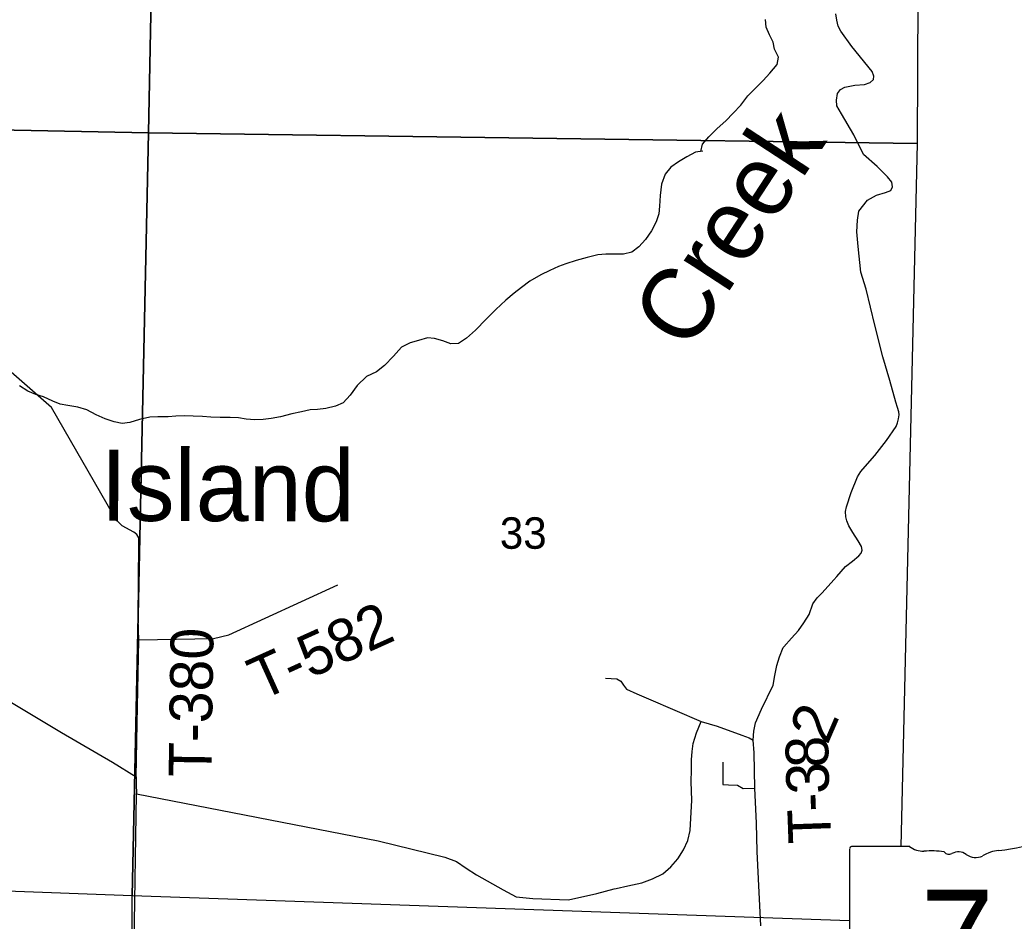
# Model space of a CAD drawing. Extents: x 0 to 34, y 0 to 22.
# Drawn here: x 6.245 to 7.567, y 15.005 to 16.204 of the extents above; entities that cross this region are included whole.
import ezdxf

# ---------------------------------------------------------------- set-up
doc = ezdxf.new("R2010")
doc.units = 0
for name, color, linetype in [('Default', 7, 'Continuous'), ('GM_X_Minor_River', 7, 'Continuous'), ('GM_X_Minor_River_Text', 7, 'Continuous'), ('GM_X_Section', 7, 'Continuous'), ('GM_X_Section_Text', 7, 'Continuous'), ('GM_X_State_Shield', 7, 'Continuous'), ('GM_X_Township_Road', 7, 'Continuous'), ('GM_X_Township_Road_Text', 7, 'Continuous')]:
    doc.layers.add(name, color=color, linetype=linetype)

msp = doc.modelspace()

# ---------------------------------------------------------------- linework, layer by layer
at = {"layer": 'Default'}
for p, q in [((6.3944, 15.0386), (5.4229, 15.0756)), ((6.3909, 14.1), (6.3944, 15.0386))]:
    msp.add_line(p, q, dxfattribs=at)
at = {"layer": 'GM_X_Minor_River'}
for p, q in [((7.2369, 16.1939), (7.2363, 16.2042)), ((7.2414, 16.1838), (7.2369, 16.1939)), ((7.2466, 16.174), (7.2414, 16.1838)), ((7.248, 16.1645), (7.2466, 16.174)), ((7.2536, 16.154), (7.248, 16.1645)), ((7.2519, 16.1441), (7.2536, 16.154)), ((7.242, 16.1328), (7.2519, 16.1441)), ((7.2331, 16.123), (7.242, 16.1328)), ((7.2128, 16.1027), (7.2231, 16.1129)), ((7.2231, 16.1129), (7.2331, 16.123)), ((7.2036, 16.0903), (7.2128, 16.1027)), ((7.1933, 16.0793), (7.2036, 16.0903)), ((7.1836, 16.0695), (7.1933, 16.0793)), ((7.1607, 16.048), (7.1718, 16.0593)), ((7.1718, 16.0593), (7.1836, 16.0695)), ((7.1526, 16.0383), (7.1607, 16.048)), ((7.1501, 16.0287), (7.1526, 16.0383)), ((7.1316, 16.0215), (7.1204, 16.0147)), ((7.1432, 16.0276), (7.1316, 16.0215)), ((7.1527, 16.0291), (7.1432, 16.0276)), ((7.1103, 16.0079), (7.1027, 15.9982)), ((7.1204, 16.0147), (7.1103, 16.0079)), ((7.1027, 15.9982), (7.0981, 15.9851)), ((7.0981, 15.9851), (7.0963, 15.9702)), ((7.0963, 15.9702), (7.0952, 15.9557)), ((7.0952, 15.9557), (7.0944, 15.9458)), ((7.0944, 15.9458), (7.0909, 15.935)), ((7.0909, 15.935), (7.0845, 15.923)), ((7.0845, 15.923), (7.0769, 15.9114)), ((7.068, 15.9016), (7.0584, 15.8948)), ((7.0769, 15.9114), (7.068, 15.9016)), ((6.9993, 15.8877), (6.9846, 15.8834)), ((7.0132, 15.8911), (6.9993, 15.8877)), ((7.0239, 15.8918), (7.0132, 15.8911)), ((7.0337, 15.8918), (7.0239, 15.8918)), ((7.0474, 15.8918), (7.0337, 15.8918)), ((7.0584, 15.8948), (7.0474, 15.8918)), ((6.9609, 15.8754), (6.9496, 15.8701)), ((6.9706, 15.8791), (6.9609, 15.8754)), ((6.9846, 15.8834), (6.9706, 15.8791)), ((6.9376, 15.8644), (6.9227, 15.856)), ((6.9496, 15.8701), (6.9376, 15.8644)), ((6.9119, 15.8476), (6.9023, 15.8401)), ((6.9227, 15.856), (6.9119, 15.8476)), ((6.9023, 15.8401), (6.8912, 15.831)), ((6.8912, 15.831), (6.8779, 15.8184)), ((6.8779, 15.8184), (6.865, 15.8055)), ((6.865, 15.8055), (6.8506, 15.7909)), ((6.8506, 15.7909), (6.8388, 15.7803)), ((6.7525, 15.7681), (6.7418, 15.7563)), ((6.7637, 15.7741), (6.7525, 15.7681)), ((6.775, 15.7772), (6.7637, 15.7741)), ((6.7867, 15.7806), (6.775, 15.7772)), ((6.7962, 15.7797), (6.7867, 15.7806)), ((6.8073, 15.7767), (6.7962, 15.7797)), ((6.8177, 15.7728), (6.8073, 15.7767)), ((6.828, 15.7731), (6.8177, 15.7728)), ((6.8388, 15.7803), (6.828, 15.7731)), ((6.7418, 15.7563), (6.7296, 15.7438)), ((6.7296, 15.7438), (6.7193, 15.7355)), ((6.7058, 15.7293), (6.6932, 15.7172)), ((6.7193, 15.7355), (6.7058, 15.7293)), ((6.2555, 15.7099), (6.2446, 15.7168)), ((6.6932, 15.7172), (6.6841, 15.7047)), ((6.2663, 15.7053), (6.2555, 15.7099)), ((6.2766, 15.7022), (6.2663, 15.7053)), ((6.289, 15.6965), (6.2766, 15.7022)), ((6.6841, 15.7047), (6.6749, 15.6945)), ((6.2986, 15.6923), (6.289, 15.6965)), ((6.3089, 15.6907), (6.2986, 15.6923)), ((6.3219, 15.6884), (6.3089, 15.6907)), ((6.6644, 15.69), (6.6516, 15.6866)), ((6.6749, 15.6945), (6.6644, 15.69)), ((6.3338, 15.685), (6.3219, 15.6884)), ((6.3466, 15.6785), (6.3338, 15.685)), ((6.3585, 15.6728), (6.3466, 15.6785)), ((6.4284, 15.6758), (6.4178, 15.6751)), ((6.4421, 15.6758), (6.4284, 15.6758)), ((6.4523, 15.6765), (6.4421, 15.6758)), ((6.4637, 15.6769), (6.4523, 15.6765)), ((6.4755, 15.6765), (6.4637, 15.6769)), ((6.4877, 15.6761), (6.4755, 15.6765)), ((6.4987, 15.6753), (6.4877, 15.6761)), ((6.5915, 15.6756), (6.579, 15.6733)), ((6.6066, 15.6798), (6.5915, 15.6756)), ((6.6194, 15.6825), (6.6066, 15.6798)), ((6.6307, 15.6848), (6.6194, 15.6825)), ((6.6406, 15.6855), (6.6307, 15.6848)), ((6.6516, 15.6866), (6.6406, 15.6855)), ((6.3704, 15.669), (6.3585, 15.6728)), ((6.3808, 15.6667), (6.3704, 15.669)), ((6.391, 15.6681), (6.3808, 15.6667)), ((6.4042, 15.672), (6.391, 15.6681)), ((6.4178, 15.6751), (6.4042, 15.672)), ((6.5113, 15.6746), (6.4987, 15.6753)), ((6.5246, 15.6746), (6.5113, 15.6746)), ((6.5357, 15.6742), (6.5246, 15.6746)), ((6.5456, 15.6726), (6.5357, 15.6742)), ((6.5574, 15.6718), (6.5456, 15.6726)), ((6.5684, 15.6722), (6.5574, 15.6718)), ((6.579, 15.6733), (6.5684, 15.6722))]:
    msp.add_line(p, q, dxfattribs=at)
at = {"layer": 'GM_X_Section'}
for p, q in [((6.4161, 16.0534), (6.4366, 17.1114)), ((6.4366, 17.1114), (6.4161, 16.0534)), ((7.441, 17.0998), (7.438, 16.0393)), ((6.4161, 16.0534), (5.4597, 16.0717)), ((5.4597, 16.0717), (6.4161, 16.0534)), ((6.4161, 16.0534), (6.3944, 15.0386)), ((6.3944, 15.0386), (6.4161, 16.0534)), ((7.438, 16.0393), (6.4161, 16.0534)), ((6.4161, 16.0534), (7.438, 16.0393)), ((7.438, 16.0393), (7.4162, 15.1044)), ((6.3944, 15.0386), (5.4229, 15.0756)), ((7.348, 15.0053), (6.3944, 15.0386))]:
    msp.add_line(p, q, dxfattribs=at)
at = {"layer": 'GM_X_State_Shield'}
for p, q in [((7.348, 15.1009), (7.348, 14.9008)), ((7.4279, 15.1044), (7.3506, 15.1044))]:
    msp.add_line(p, q, dxfattribs=at)
for centre, radius, start, end in [((7.5178, 15.3772), 0.2796, 275.8445, 288.9065), ((7.3511, 15.1014), 0.00305, 98.1301, 188.1301), ((7.4462, 15.1276), 0.0296, 231.6195, 271.1119), ((7.4561, 14.992), 0.1064, 80.4867, 94.9883), ((7.4802, 15.1024), 0.00855, 219.7921, 297.1024), ((7.4928, 15.0793), 0.0178, 54.4667, 119.1411), ((7.5535, 15.0433), 0.0563, 97.3462, 120.7689), ((7.5157, 15.111), 0.0214, 233.8562, 294.8282)]:
    msp.add_arc(centre, radius, start, end, dxfattribs=at)
at = {"layer": 'GM_X_Township_Road'}
for p, q in [((7.3309, 16.203), (7.3295, 16.2115)), ((7.3327, 16.1954), (7.3309, 16.203)), ((7.3365, 16.1886), (7.3327, 16.1954)), ((7.3508, 16.1681), (7.3365, 16.1886)), ((7.3781, 16.1351), (7.3508, 16.1681)), ((7.38, 16.1287), (7.3781, 16.1351)), ((7.3798, 16.1243), (7.38, 16.1287)), ((7.3361, 16.1112), (7.3415, 16.1139)), ((7.3415, 16.1139), (7.3548, 16.1169)), ((7.3548, 16.1169), (7.3677, 16.1178)), ((7.3677, 16.1178), (7.3753, 16.1205)), ((7.3753, 16.1205), (7.3798, 16.1243)), ((7.3304, 16.0966), (7.3317, 16.1055)), ((7.3317, 16.1055), (7.3361, 16.1112)), ((7.3311, 16.0894), (7.3304, 16.0966)), ((7.3373, 16.0786), (7.3311, 16.0894)), ((7.3538, 16.0506), (7.3373, 16.0786)), ((7.3665, 16.0245), (7.3538, 16.0506)), ((7.3848, 16.0084), (7.3665, 16.0245)), ((7.3984, 15.9947), (7.3848, 16.0084)), ((7.4041, 15.9878), (7.3984, 15.9947)), ((7.4027, 15.9768), (7.405, 15.9817)), ((7.405, 15.9817), (7.4041, 15.9878)), ((7.372, 15.9638), (7.3836, 15.9705)), ((7.3836, 15.9705), (7.3958, 15.9739)), ((7.3958, 15.9739), (7.4027, 15.9768)), ((7.3601, 15.949), (7.372, 15.9638)), ((7.3583, 15.9374), (7.3601, 15.949)), ((7.3577, 15.9217), (7.3583, 15.9374)), ((7.3593, 15.9022), (7.3577, 15.9217)), ((7.363, 15.8681), (7.3593, 15.9022)), ((7.3699, 15.8455), (7.363, 15.8681)), ((7.3815, 15.7975), (7.3699, 15.8455)), ((7.3924, 15.7553), (7.3815, 15.7975)), ((6.2869, 15.6882), (6.1959, 15.7676)), ((7.4015, 15.724), (7.3924, 15.7553)), ((7.4096, 15.6953), (7.4015, 15.724)), ((7.4116, 15.6879), (7.4096, 15.6953)), ((6.3693, 15.545), (6.2869, 15.6882)), ((7.4133, 15.6823), (7.4116, 15.6879)), ((7.4132, 15.6732), (7.4137, 15.6782)), ((7.4137, 15.6782), (7.4133, 15.6823)), ((7.397, 15.6443), (7.4098, 15.663)), ((7.4098, 15.663), (7.4119, 15.6678)), ((7.4119, 15.6678), (7.4132, 15.6732)), ((7.3814, 15.6244), (7.397, 15.6443)), ((7.372, 15.613), (7.3814, 15.6244)), ((7.3631, 15.6028), (7.372, 15.613)), ((7.3586, 15.5959), (7.3631, 15.6028)), ((7.3501, 15.5752), (7.3586, 15.5959)), ((7.3439, 15.5559), (7.3501, 15.5752)), ((6.3748, 15.5367), (6.3693, 15.545)), ((7.3424, 15.5496), (7.3439, 15.5559)), ((7.3431, 15.5427), (7.3424, 15.5496)), ((6.3811, 15.5307), (6.3748, 15.5367)), ((6.3965, 15.5221), (6.3811, 15.5307)), ((7.3443, 15.5375), (7.3431, 15.5427)), ((7.3472, 15.5308), (7.3443, 15.5375)), ((7.3525, 15.5217), (7.3472, 15.5308)), ((6.4004, 15.5191), (6.3965, 15.5221)), ((6.403, 15.5146), (6.4004, 15.5191)), ((7.3594, 15.5107), (7.3525, 15.5217)), ((6.4023, 15.4071), (6.4031, 15.5071)), ((6.4031, 15.5071), (6.403, 15.5146)), ((7.3637, 15.5034), (7.3594, 15.5107)), ((7.3517, 15.4838), (7.3601, 15.4906)), ((7.3601, 15.4906), (7.3632, 15.4943)), ((7.3632, 15.4943), (7.3645, 15.4985)), ((7.3645, 15.4985), (7.3637, 15.5034)), ((7.3426, 15.4768), (7.3517, 15.4838)), ((7.3309, 15.4635), (7.3426, 15.4768)), ((6.5227, 15.3856), (6.6675, 15.4522)), ((7.3194, 15.4505), (7.3269, 15.4589)), ((7.3269, 15.4589), (7.3309, 15.4635)), ((7.3049, 15.4351), (7.311, 15.441)), ((7.311, 15.441), (7.3194, 15.4505)), ((7.2943, 15.4128), (7.2992, 15.427)), ((7.2992, 15.427), (7.3049, 15.4351)), ((7.2872, 15.4015), (7.2943, 15.4128)), ((6.4027, 15.3924), (6.4023, 15.4071)), ((7.2799, 15.3917), (7.2872, 15.4015)), ((6.4031, 15.379), (6.4027, 15.3924)), ((6.5026, 15.3809), (6.5227, 15.3856)), ((7.2706, 15.3813), (7.2799, 15.3917)), ((6.4011, 15.2676), (6.4031, 15.379)), ((6.4031, 15.379), (6.5026, 15.3809)), ((7.2606, 15.3698), (7.2706, 15.3813)), ((7.2546, 15.3564), (7.2599, 15.369)), ((7.2599, 15.369), (7.2606, 15.3698)), ((7.2511, 15.3448), (7.2546, 15.3564)), ((7.2486, 15.3316), (7.2511, 15.3448)), ((7.0237, 15.3279), (7.0386, 15.3273)), ((7.0386, 15.3273), (7.044, 15.3242)), ((7.044, 15.3242), (7.0474, 15.3186)), ((7.0474, 15.3186), (7.0515, 15.3134)), ((7.2307, 15.2871), (7.2462, 15.3189)), ((7.2462, 15.3189), (7.2486, 15.3316)), ((7.0515, 15.3134), (7.065, 15.3074)), ((7.065, 15.3074), (7.0808, 15.3006)), ((6.2316, 15.2969), (6.3003, 15.256)), ((7.0808, 15.3006), (7.1509, 15.2707)), ((7.2227, 15.2689), (7.2307, 15.2871)), ((6.3998, 15.1967), (6.4011, 15.2676)), ((7.1443, 15.2555), (7.1509, 15.2707)), ((7.1509, 15.2707), (7.1721, 15.2643)), ((7.2207, 15.2576), (7.2227, 15.2689)), ((6.3003, 15.256), (6.368, 15.2162)), ((7.1399, 15.2413), (7.1443, 15.2555)), ((7.1721, 15.2643), (7.2048, 15.2525)), ((7.2196, 15.2455), (7.2207, 15.2576)), ((7.1387, 15.2305), (7.1399, 15.2413)), ((7.2048, 15.2525), (7.2144, 15.2486)), ((7.2144, 15.2486), (7.2196, 15.2455)), ((7.2211, 15.2288), (7.2196, 15.2455)), ((7.1379, 15.2196), (7.1387, 15.2305)), ((7.2219, 15.1816), (7.2211, 15.2288)), ((6.368, 15.2162), (6.3998, 15.1967)), ((7.1379, 15.2063), (7.1379, 15.2196)), ((7.1795, 15.2166), (7.1795, 15.1865)), ((7.1376, 15.1904), (7.1379, 15.2063)), ((6.3998, 15.1967), (6.3998, 15.187)), ((6.3998, 15.187), (6.4001, 15.1741)), ((7.1383, 15.166), (7.1376, 15.1904)), ((7.1795, 15.1865), (7.1868, 15.1863)), ((6.397, 14.9697), (6.4001, 15.1741)), ((6.4001, 15.1741), (6.7213, 15.1117)), ((7.1868, 15.1863), (7.199, 15.186)), ((7.199, 15.186), (7.2067, 15.1813)), ((7.2067, 15.1813), (7.2219, 15.1816)), ((7.2226, 15.1725), (7.2219, 15.1816)), ((7.1362, 15.1253), (7.1383, 15.166)), ((7.2244, 15.1351), (7.2226, 15.1725)), ((7.2253, 15.0975), (7.2244, 15.1351)), ((7.1328, 15.1122), (7.1362, 15.1253)), ((6.7213, 15.1117), (6.8101, 15.09)), ((7.1273, 15.0996), (7.1328, 15.1122)), ((7.1196, 15.0879), (7.1273, 15.0996)), ((7.2269, 15.0611), (7.2253, 15.0975)), ((6.8101, 15.09), (6.8253, 15.0845)), ((6.8253, 15.0845), (6.8384, 15.0753)), ((7.1102, 15.0773), (7.1196, 15.0879)), ((6.8384, 15.0753), (6.8521, 15.0664)), ((7.0859, 15.0613), (7.0996, 15.0679)), ((7.0996, 15.0679), (7.1102, 15.0773)), ((6.8521, 15.0664), (6.8875, 15.0467)), ((7.0531, 15.0521), (7.0716, 15.0561)), ((7.0716, 15.0561), (7.0859, 15.0613)), ((7.2299, 14.9986), (7.2269, 15.0611)), ((6.8875, 15.0467), (6.9046, 15.0375)), ((6.9745, 15.0334), (7.0119, 15.0417)), ((7.0119, 15.0417), (7.0349, 15.0478)), ((7.0349, 15.0478), (7.0378, 15.0485)), ((7.0378, 15.0485), (7.0531, 15.0521)), ((6.9046, 15.0375), (6.9269, 15.0349)), ((6.9269, 15.0349), (6.9745, 15.0334))]:
    msp.add_line(p, q, dxfattribs=at)

# ---------------------------------------------------------------- texts
at = {"layer": 'GM_X_Minor_River_Text'}
for s, height, rotation, p in [('Creek', 0.09471, 56.8088, (7.1337, 15.76)), ('Island', 0.0947, 359.8692, (6.3521, 15.5374))]:
    msp.add_text(s, height=height, rotation=rotation, dxfattribs=at).set_placement(p)
at = {"layer": 'GM_X_Section_Text'}
msp.add_text('33', height=0.04186, rotation=0, dxfattribs=at).set_placement((6.883, 15.5002))
at = {"layer": 'GM_X_State_Shield'}
msp.add_text('7', height=0.1318, dxfattribs=at).set_placement((7.4421, 14.9149))
at = {"layer": 'GM_X_Township_Road_Text'}
for s, height, rotation, p in [('T-582', 0.05682, 24.3044, (6.5656, 15.2978)), ('T-380', 0.05682, 89.1579, (6.4995, 15.1962)), ('2', 0.0568, 66.6483, (7.3184, 15.2382)), ('8', 0.0568, 90.6297, (7.32, 15.2094)), ('3', 0.0568, 91.9884, (7.3212, 15.1747)), ('-', 0.0568, 92.073, (7.322, 15.1514)), ('T', 0.0568, 92.0618, (7.3236, 15.109))]:
    msp.add_text(s, height=height, rotation=rotation, dxfattribs=at).set_placement(p)

doc.saveas('drawing.dxf')
